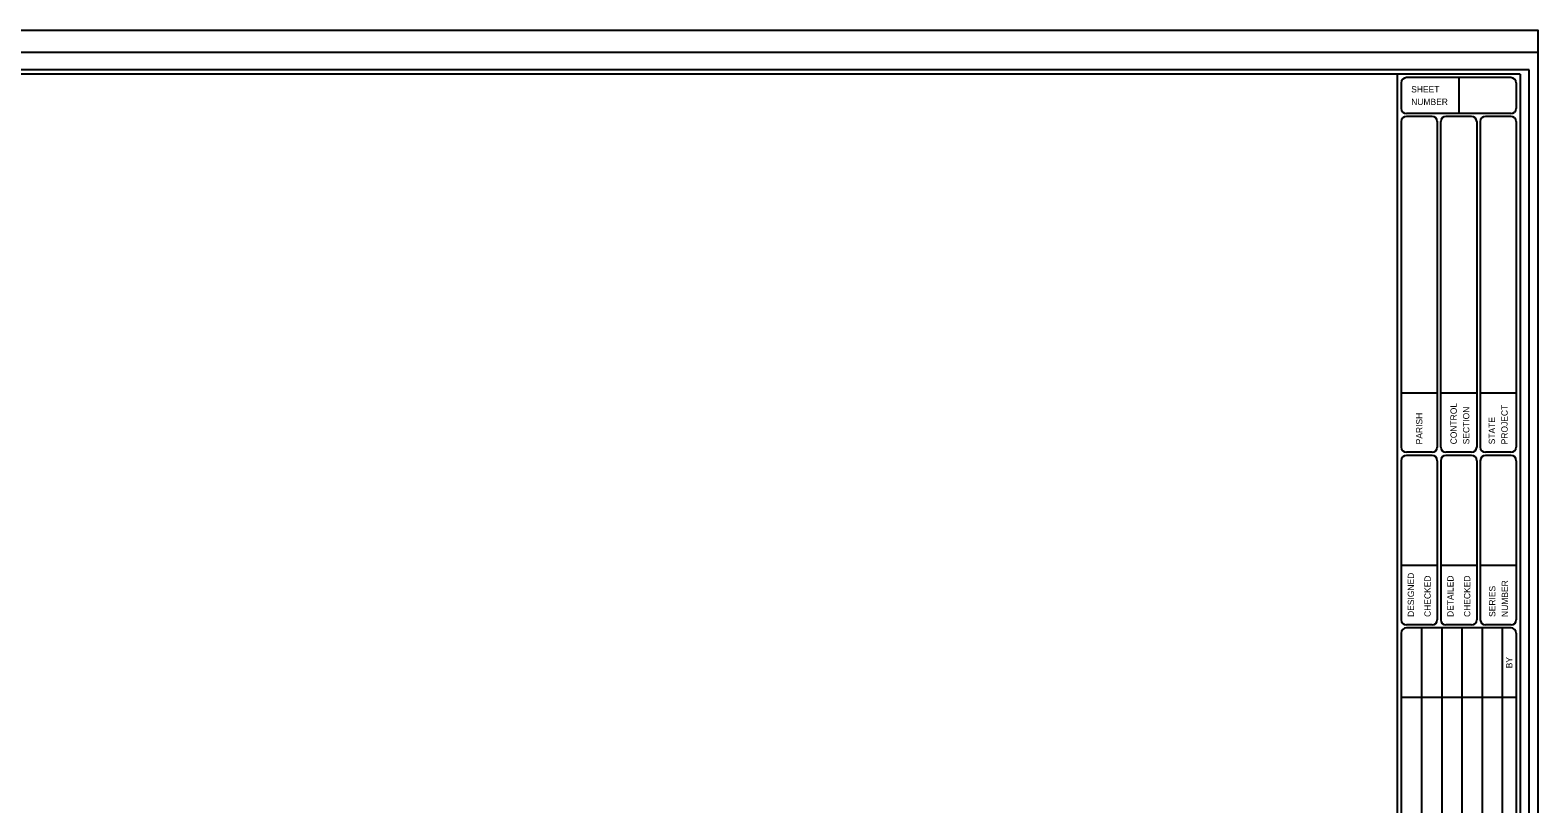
# Model space of a CAD drawing. Extents: x -1.93 to 2.83, y -1.79 to 1.85.
# Drawn here: x 1.404 to 2.833, y 1.1 to 1.833 of the extents above; entities that cross this region are included whole.
import ezdxf

# ---------------------------------------------------------------- set-up
doc = ezdxf.new("R2010")
doc.units = 0
for name, color, linetype in [('Plot Border', 7, 'Continuous'), ('Plot Border 2', 7, 'Continuous'), ('Sheet Border', 7, 'Continuous')]:
    doc.layers.add(name, color=color, linetype=linetype)

msp = doc.modelspace()

# ---------------------------------------------------------------- linework, layer by layer
at = {"layer": 'Plot Border'}
for points in [[(0, 1.8333), (2.8333, 1.8333), (2.8333, 0), (0, 0)], [(2.825, 1.7958), (0.075, 1.7958), (0.075, 0.0375), (2.825, 0.0375)]]:
    msp.add_lwpolyline(points, close=True, dxfattribs=at)
at = {"layer": 'Plot Border 2'}
msp.add_lwpolyline([(0, 1.8125), (2.8333, 1.8125), (2.8333, 0.0208), (0, 0.0208)], close=True, dxfattribs=at)
at = {"layer": 'Sheet Border'}
for p, q in [((2.8167, 1.7917), (0.1917, 1.7917)), ((2.7, 1.7917), (2.7, 0.0417)), ((2.8079, 1.7884), (2.7088, 1.7884)), ((2.7583, 1.7884), (2.7583, 1.7543)), ((2.8167, 1.7917), (2.8167, 0.0417)), ((2.7039, 1.7834), (2.7039, 1.7592)), ((2.8128, 1.7834), (2.8128, 1.7592)), ((2.7039, 1.747), (2.7039, 1.4379)), ((2.8079, 1.7543), (2.7088, 1.7543)), ((2.733, 1.7516), (2.7088, 1.7516)), ((2.7379, 1.7471), (2.7379, 1.4378)), ((2.7412, 1.7467), (2.7412, 1.4382)), ((2.7704, 1.7516), (2.7462, 1.7516)), ((2.7754, 1.7467), (2.7754, 1.4382)), ((2.7787, 1.7467), (2.7787, 1.4382)), ((2.8079, 1.7516), (2.7836, 1.7516)), ((2.8128, 1.7467), (2.8128, 1.4382)), ((2.7379, 1.4894), (2.7039, 1.4894)), ((2.7754, 1.4894), (2.7412, 1.4894)), ((2.8128, 1.4894), (2.7787, 1.4894)), ((2.733, 1.4333), (2.7088, 1.4333)), ((2.733, 1.4302), (2.7088, 1.4302)), ((2.7704, 1.4333), (2.7462, 1.4333)), ((2.7705, 1.4302), (2.7462, 1.4302)), ((2.8079, 1.4333), (2.7836, 1.4333)), ((2.8079, 1.4302), (2.7837, 1.4302)), ((2.7039, 1.4257), (2.7039, 1.2746)), ((2.738, 1.4253), (2.738, 1.2746)), ((2.7413, 1.4257), (2.7413, 1.2746)), ((2.7754, 1.4253), (2.7754, 1.2746)), ((2.7787, 1.4257), (2.7787, 1.2746)), ((2.8129, 1.4253), (2.8129, 1.2746)), ((2.7379, 1.3258), (2.7039, 1.3258)), ((2.7754, 1.3258), (2.7412, 1.3258)), ((2.8128, 1.3258), (2.7787, 1.3258)), ((2.7039, 1.2619), (2.7039, 0.7034)), ((2.733, 1.2697), (2.7088, 1.2697)), ((2.8079, 1.2668), (2.7088, 1.2668)), ((2.723, 1.2668), (2.723, 0.6985)), ((2.7422, 1.2668), (2.7422, 0.6985)), ((2.7705, 1.2697), (2.7462, 1.2697)), ((2.7613, 1.2668), (2.7613, 0.6985)), ((2.7805, 1.2668), (2.7805, 0.6985)), ((2.8079, 1.2697), (2.7837, 1.2697)), ((2.7996, 1.2668), (2.7996, 0.6985)), ((2.8128, 1.2619), (2.8128, 0.7034)), ((2.8128, 1.2008), (2.7039, 1.2008))]:
    msp.add_line(p, q, dxfattribs=at)
for centre, start, end in [((2.7088, 1.7834), 90, 180), ((2.8078, 1.7834), 0, 90), ((2.7088, 1.7592), 180, 270), ((2.8078, 1.7592), 270, 0), ((2.7088, 1.7467), 90, 180), ((2.733, 1.7467), 0, 90), ((2.7462, 1.7467), 90, 180), ((2.7704, 1.7467), 0, 90), ((2.7836, 1.7467), 90, 180), ((2.8078, 1.7467), 0, 90), ((2.7088, 1.4382), 180, 270), ((2.7088, 1.4253), 90, 180), ((2.733, 1.4382), 270, 0), ((2.733, 1.4253), 0, 90), ((2.7462, 1.4382), 180, 270), ((2.7462, 1.4253), 90, 180), ((2.7704, 1.4382), 270, 0), ((2.7705, 1.4253), 0, 90), ((2.7836, 1.4382), 180, 270), ((2.7837, 1.4253), 90, 180), ((2.8078, 1.4382), 270, 0), ((2.8079, 1.4253), 0, 90), ((2.7088, 1.2746), 180, 270), ((2.733, 1.2746), 270, 0), ((2.7462, 1.2746), 180, 270), ((2.7705, 1.2746), 270, 0), ((2.7837, 1.2746), 180, 270), ((2.8079, 1.2746), 270, 0), ((2.7088, 1.2619), 90, 180), ((2.8078, 1.2619), 0, 90)]:
    msp.add_arc(centre, 0.00495, start, end, dxfattribs=at)

# ---------------------------------------------------------------- texts
for s, p in [('SHEET', (2.7133, 1.7743)), ('NUMBER', (2.7133, 1.7624))]:
    msp.add_text(s, height=0.006, dxfattribs=at).set_placement(p)
for s, p in [('CONTROL', (2.7565, 1.4408)), ('SECTION', (2.7684, 1.4408)), ('PROJECT', (2.8047, 1.4408)), ('PARISH', (2.7239, 1.4408)), ('STATE', (2.7928, 1.4408)), ('DESIGNED', (2.716, 1.2772)), ('CHECKED', (2.7318, 1.2772)), ('DETAILED', (2.7534, 1.2772)), ('CHECKED', (2.7693, 1.2772)), ('SERIES', (2.7931, 1.2772)), ('NUMBER', (2.8051, 1.2772)), ('BY', (2.8092, 1.2285))]:
    msp.add_text(s, height=0.006, rotation=90, dxfattribs=at).set_placement(p)

doc.saveas('drawing.dxf')
